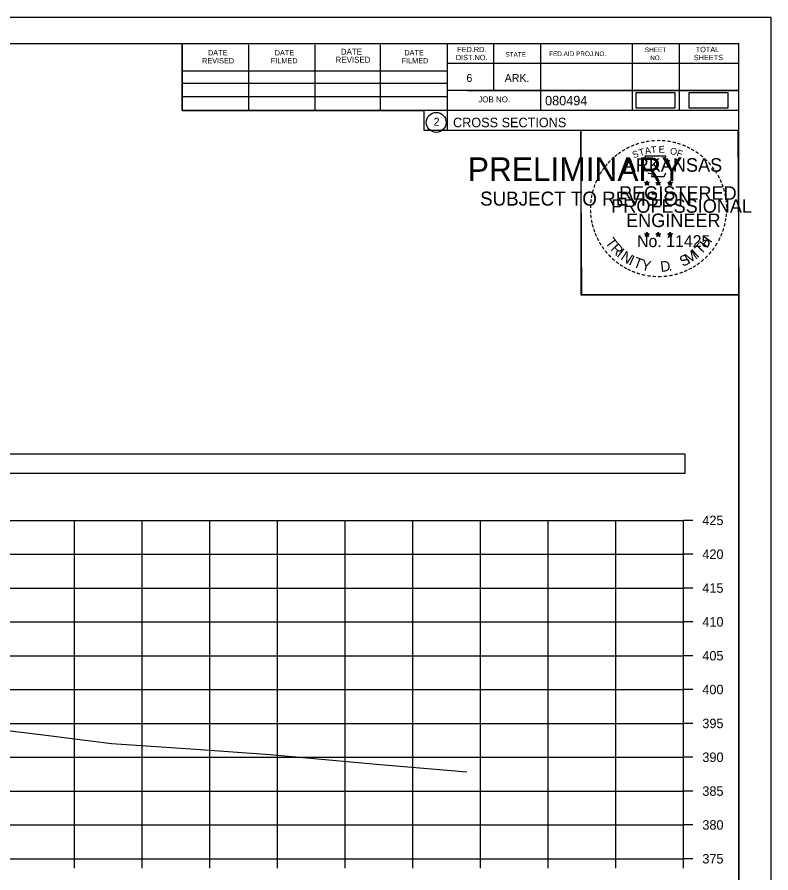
# Model space of a CAD drawing. Extents: x 1376273 to 1384221, y 378927 to 384592.
# Drawn here: x 1378276 to 1378387.4, y 380838.7 to 380965.2 of the extents above; entities that cross this region are included whole.
import ezdxf

# ---------------------------------------------------------------- set-up
doc = ezdxf.new("R2010")
doc.units = 0
for name, color, linetype in [('R_Axis', 7, 'Continuous'), ('R_Axis Annot', 7, 'Continuous'), ('R_Border', 7, 'Continuous'), ('R_Border PE', 7, 'Continuous'), ('R_Border Prem', 7, 'Continuous'), ('R_Drive', 7, 'Continuous'), ('R_Exist Surface', 7, 'Continuous'), ('R_Grid', 7, 'Continuous'), ('R_No Plot', 7, 'Continuous')]:
    doc.layers.add(name, color=color, linetype=linetype)

msp = doc.modelspace()

# ---------------------------------------------------------------- linework, layer by layer
at = {"layer": 'R_Axis'}
for p, q in [((1378374.46, 380840.83), (1378374.46, 380890.83)), ((1378375.86, 380890.83), (1378374.46, 380890.83)), ((1378375.86, 380885.83), (1378374.46, 380885.83)), ((1378375.86, 380880.83), (1378374.46, 380880.83)), ((1378375.86, 380875.83), (1378374.46, 380875.83)), ((1378375.86, 380870.83), (1378374.46, 380870.83)), ((1378375.86, 380865.83), (1378374.46, 380865.83)), ((1378375.86, 380860.83), (1378374.46, 380860.83)), ((1378375.86, 380855.83), (1378374.46, 380855.83)), ((1378375.86, 380850.83), (1378374.46, 380850.83)), ((1378375.86, 380845.83), (1378374.46, 380845.83)), ((1378074.46, 380840.83), (1378374.46, 380840.83)), ((1378284.46, 380839.43), (1378284.46, 380840.83)), ((1378294.46, 380839.43), (1378294.46, 380840.83)), ((1378304.46, 380839.43), (1378304.46, 380840.83)), ((1378314.46, 380839.43), (1378314.46, 380840.83)), ((1378324.46, 380839.43), (1378324.46, 380840.83)), ((1378334.46, 380839.43), (1378334.46, 380840.83)), ((1378344.46, 380839.43), (1378344.46, 380840.83)), ((1378354.46, 380839.43), (1378354.46, 380840.83)), ((1378364.46, 380839.43), (1378364.46, 380840.83)), ((1378374.46, 380839.43), (1378374.46, 380840.83)), ((1378375.86, 380840.83), (1378374.46, 380840.83))]:
    msp.add_line(p, q, dxfattribs=at)
at = {"layer": 'R_Axis Annot'}
msp.add_lwpolyline([(1378072.9, 380897.78), (1378374.7, 380897.78), (1378374.7, 380900.59), (1378072.9, 380900.59)], close=True, dxfattribs=at)
at = {"layer": 'R_Border'}
for p, q in [((1378066.46, 380961.29), (1378382.64, 380961.29)), ((1378300.38, 380951.41), (1378300.38, 380961.29)), ((1378339.54, 380961.29), (1378339.54, 380948.49)), ((1378346.38, 380961.29), (1378346.38, 380954.35)), ((1378353.32, 380961.29), (1378353.32, 380951.41)), ((1378366.9, 380961.29), (1378366.9, 380951.41)), ((1378373.84, 380961.29), (1378373.84, 380951.41)), ((1378382.64, 380755.83), (1378382.64, 380961.29)), ((1378310.24, 380951.41), (1378310.24, 380961.09)), ((1378320, 380951.41), (1378320, 380961.09)), ((1378329.68, 380951.41), (1378329.68, 380961.09)), ((1378382.64, 380958.35), (1378339.54, 380958.35)), ((1378382.64, 380958.37), (1378382.64, 380958.37)), ((1378300.38, 380957.27), (1378339.54, 380957.27)), ((1378300.38, 380955.41), (1378339.54, 380955.41)), ((1378382.64, 380954.35), (1378339.54, 380954.35)), ((1378342.5, 380954.35), (1378382.64, 380954.35)), ((1378300.38, 380951.41), (1378300.38, 380953.47)), ((1378300.38, 380953.47), (1378339.54, 380953.47)), ((1378382.64, 380951.41), (1378300.38, 380951.41)), ((1378339.54, 380948.49), (1378382.64, 380948.49))]:
    msp.add_line(p, q, dxfattribs=at)
msp.add_circle((1378337.92, 380949.63), 1.47, dxfattribs=at)
at = {"layer": 'R_Border PE'}
for p, q in [((1378368.72, 380940.75), (1378369.07, 380940.64)), ((1378368.72, 380940.75), (1378368.98, 380940.7)), ((1378368.72, 380940.75), (1378368.96, 380940.63)), ((1378368.86, 380940.34), (1378369.07, 380940.64)), ((1378368.86, 380940.34), (1378368.98, 380940.58)), ((1378368.86, 380940.34), (1378369.07, 380940.56)), ((1378369.07, 380941), (1378369.03, 380940.75)), ((1378369.07, 380940.64), (1378369.07, 380941)), ((1378369.07, 380941), (1378369.12, 380940.75)), ((1378369.42, 380940.75), (1378369.07, 380940.64)), ((1378369.28, 380940.34), (1378369.07, 380940.64)), ((1378369.28, 380940.34), (1378369.07, 380940.55)), ((1378369.42, 380940.75), (1378369.13, 380940.7)), ((1378369.28, 380940.34), (1378369.15, 380940.63)), ((1378369.42, 380940.75), (1378369.21, 380940.65)), ((1378370.39, 380940.75), (1378370.74, 380940.64)), ((1378370.39, 380940.75), (1378370.65, 380940.7)), ((1378370.39, 380940.75), (1378370.63, 380940.63)), ((1378370.53, 380940.34), (1378370.74, 380940.64)), ((1378370.53, 380940.34), (1378370.65, 380940.58)), ((1378370.53, 380940.34), (1378370.74, 380940.56)), ((1378370.74, 380941), (1378370.7, 380940.75)), ((1378370.74, 380940.64), (1378370.74, 380941)), ((1378370.74, 380941), (1378370.79, 380940.75)), ((1378371.09, 380940.75), (1378370.74, 380940.64)), ((1378370.95, 380940.34), (1378370.74, 380940.64)), ((1378370.95, 380940.34), (1378370.74, 380940.55)), ((1378371.09, 380940.75), (1378370.8, 380940.7)), ((1378370.95, 380940.34), (1378370.82, 380940.63)), ((1378371.09, 380940.75), (1378370.88, 380940.65)), ((1378372.16, 380940.74), (1378372.51, 380940.62)), ((1378372.16, 380940.74), (1378372.41, 380940.69)), ((1378372.16, 380940.74), (1378372.39, 380940.61)), ((1378372.29, 380940.33), (1378372.51, 380940.62)), ((1378372.29, 380940.33), (1378372.42, 380940.57)), ((1378372.29, 380940.33), (1378372.5, 380940.54)), ((1378372.51, 380940.99), (1378372.46, 380940.74)), ((1378372.72, 380940.33), (1378372.5, 380940.54)), ((1378372.51, 380940.62), (1378372.51, 380940.99)), ((1378372.51, 380940.99), (1378372.55, 380940.74)), ((1378372.85, 380940.74), (1378372.51, 380940.62)), ((1378372.72, 380940.33), (1378372.51, 380940.62)), ((1378372.85, 380940.74), (1378372.57, 380940.69)), ((1378372.72, 380940.33), (1378372.58, 380940.62)), ((1378372.85, 380940.74), (1378372.65, 380940.63)), ((1378368.72, 380933.17), (1378369.07, 380933.06)), ((1378368.72, 380933.17), (1378368.97, 380933.13)), ((1378368.72, 380933.17), (1378368.96, 380933.05)), ((1378368.85, 380932.77), (1378369.07, 380933.06)), ((1378368.85, 380932.77), (1378368.98, 380933.01)), ((1378368.85, 380932.77), (1378369.07, 380932.98)), ((1378369.07, 380933.43), (1378369.03, 380933.18)), ((1378369.07, 380933.06), (1378369.07, 380933.43)), ((1378369.07, 380933.43), (1378369.12, 380933.18)), ((1378369.41, 380933.17), (1378369.07, 380933.06)), ((1378369.28, 380932.77), (1378369.07, 380933.06)), ((1378369.28, 380932.77), (1378369.07, 380932.98)), ((1378369.41, 380933.17), (1378369.13, 380933.13)), ((1378369.28, 380932.77), (1378369.14, 380933.06)), ((1378369.41, 380933.17), (1378369.21, 380933.07)), ((1378370.39, 380933.17), (1378370.74, 380933.06)), ((1378370.39, 380933.17), (1378370.64, 380933.13)), ((1378370.39, 380933.17), (1378370.62, 380933.05)), ((1378370.52, 380932.77), (1378370.74, 380933.06)), ((1378370.52, 380932.77), (1378370.65, 380933.01)), ((1378370.52, 380932.77), (1378370.73, 380932.98)), ((1378370.74, 380933.43), (1378370.7, 380933.18)), ((1378370.95, 380932.77), (1378370.73, 380932.98)), ((1378370.74, 380933.06), (1378370.74, 380933.43)), ((1378370.74, 380933.43), (1378370.79, 380933.18)), ((1378371.08, 380933.17), (1378370.74, 380933.06)), ((1378370.95, 380932.77), (1378370.74, 380933.06)), ((1378371.08, 380933.17), (1378370.8, 380933.13)), ((1378370.95, 380932.77), (1378370.81, 380933.06)), ((1378371.08, 380933.17), (1378370.88, 380933.07)), ((1378372.15, 380933.16), (1378372.5, 380933.05)), ((1378372.15, 380933.16), (1378372.41, 380933.12)), ((1378372.15, 380933.16), (1378372.39, 380933.04)), ((1378372.29, 380932.76), (1378372.5, 380933.05)), ((1378372.29, 380932.76), (1378372.41, 380933)), ((1378372.29, 380932.76), (1378372.5, 380932.97)), ((1378372.5, 380933.42), (1378372.46, 380933.17)), ((1378372.5, 380933.05), (1378372.5, 380933.42)), ((1378372.5, 380933.42), (1378372.55, 380933.17)), ((1378372.85, 380933.16), (1378372.5, 380933.05)), ((1378372.72, 380932.76), (1378372.5, 380933.05)), ((1378372.72, 380932.76), (1378372.5, 380932.97)), ((1378372.85, 380933.16), (1378372.56, 380933.12)), ((1378372.72, 380932.76), (1378372.58, 380933.05)), ((1378372.85, 380933.16), (1378372.65, 380933.06))]:
    msp.add_line(p, q, dxfattribs=at)
for points in [[(1378368.76, 380944.63), (1378369.03, 380943.8)], [(1378372.27, 380943.7), (1378372.42, 380943.99), (1378371.73, 380943.96), (1378371.88, 380944.63), (1378368.76, 380944.63)], [(1378369.26, 380942.2), (1378369.26, 380942.12), (1378369.82, 380942.1), (1378369.76, 380941.62), (1378371.63, 380941.62), (1378371.84, 380942.16)], [(1378369.07, 380941), (1378369.28, 380940.34), (1378368.72, 380940.75), (1378369.42, 380940.75), (1378368.86, 380940.34), (1378369.07, 380941)], [(1378370.74, 380941), (1378370.95, 380940.34), (1378370.39, 380940.75), (1378371.09, 380940.75), (1378370.53, 380940.34), (1378370.74, 380941)], [(1378372.51, 380940.99), (1378372.72, 380940.33), (1378372.16, 380940.74), (1378372.85, 380940.74), (1378372.29, 380940.33), (1378372.51, 380940.99)], [(1378369.07, 380933.43), (1378369.28, 380932.77), (1378368.72, 380933.17), (1378369.41, 380933.17), (1378368.85, 380932.77), (1378369.07, 380933.43)], [(1378370.74, 380933.43), (1378370.95, 380932.77), (1378370.39, 380933.17), (1378371.08, 380933.17), (1378370.52, 380932.77), (1378370.74, 380933.43)], [(1378372.5, 380933.42), (1378372.72, 380932.76), (1378372.15, 380933.16), (1378372.85, 380933.16), (1378372.29, 380932.76), (1378372.5, 380933.42)]]:
    msp.add_lwpolyline(points, dxfattribs=at)
for centre, radius in [((1378369.07, 380940.64), 0.172), ((1378369.07, 380940.64), 0.145), ((1378369.07, 380940.64), 0.116), ((1378369.07, 380940.64), 0.0991), ((1378369.07, 380940.64), 0.0747), ((1378369.07, 380940.64), 0.0495), ((1378369.07, 380940.64), 0.0296), ((1378370.74, 380940.64), 0.172), ((1378370.74, 380940.64), 0.145), ((1378370.74, 380940.64), 0.116), ((1378370.74, 380940.64), 0.0991), ((1378370.74, 380940.64), 0.0747), ((1378370.74, 380940.64), 0.0495), ((1378370.74, 380940.64), 0.0296), ((1378372.5, 380940.62), 0.172), ((1378372.5, 380940.62), 0.145), ((1378372.5, 380940.62), 0.116), ((1378372.5, 380940.62), 0.0991), ((1378372.5, 380940.62), 0.0747), ((1378372.5, 380940.62), 0.0495), ((1378372.5, 380940.62), 0.0296), ((1378369.07, 380933.06), 0.172), ((1378369.07, 380933.06), 0.145), ((1378369.07, 380933.06), 0.116), ((1378369.07, 380933.06), 0.0991), ((1378369.07, 380933.06), 0.0747), ((1378369.07, 380933.06), 0.0495), ((1378369.07, 380933.06), 0.0296), ((1378370.74, 380933.06), 0.172), ((1378370.74, 380933.06), 0.145), ((1378370.74, 380933.06), 0.116), ((1378370.74, 380933.06), 0.0991), ((1378370.74, 380933.06), 0.0747), ((1378370.74, 380933.06), 0.0495), ((1378370.74, 380933.06), 0.0296), ((1378372.5, 380933.05), 0.172), ((1378372.5, 380933.05), 0.145), ((1378372.5, 380933.05), 0.116), ((1378372.5, 380933.05), 0.0991), ((1378372.5, 380933.05), 0.0747), ((1378372.5, 380933.05), 0.0495), ((1378372.5, 380933.05), 0.0296)]:
    msp.add_circle(centre, radius, dxfattribs=at)
at = {"layer": 'R_Drive'}
for points in [[(1378367.43, 380951.8), (1378373.26, 380951.8), (1378373.26, 380953.99), (1378367.43, 380953.99)], [(1378375.24, 380951.79), (1378381.08, 380951.79), (1378381.08, 380953.98), (1378375.24, 380953.98)]]:
    msp.add_lwpolyline(points, close=True, dxfattribs=at)
at = {"layer": 'R_Exist Surface'}
msp.add_lwpolyline([(1378270.5, 380860.27), (1378280.62, 380859.02), (1378289.91, 380857.87), (1378302.37, 380857), (1378313.37, 380856.25), (1378329.1, 380854.81), (1378342.46, 380853.66)], dxfattribs=at)
at = {"layer": 'R_Grid'}
for p, q in [((1378074.46, 380890.83), (1378374.46, 380890.83)), ((1378284.46, 380840.83), (1378284.46, 380890.83)), ((1378294.46, 380840.83), (1378294.46, 380890.83)), ((1378304.46, 380840.83), (1378304.46, 380890.83)), ((1378314.46, 380840.83), (1378314.46, 380890.83)), ((1378324.46, 380840.83), (1378324.46, 380890.83)), ((1378334.46, 380840.83), (1378334.46, 380890.83)), ((1378344.46, 380840.83), (1378344.46, 380890.83)), ((1378354.46, 380840.83), (1378354.46, 380890.83)), ((1378364.46, 380840.83), (1378364.46, 380890.83)), ((1378374.46, 380840.83), (1378374.46, 380890.83)), ((1378074.46, 380885.83), (1378374.46, 380885.83)), ((1378074.46, 380880.83), (1378374.46, 380880.83)), ((1378074.46, 380875.83), (1378374.46, 380875.83)), ((1378074.46, 380870.83), (1378374.46, 380870.83)), ((1378074.46, 380865.83), (1378374.46, 380865.83)), ((1378074.46, 380860.83), (1378374.46, 380860.83)), ((1378074.46, 380855.83), (1378374.46, 380855.83)), ((1378074.46, 380850.83), (1378374.46, 380850.83)), ((1378074.46, 380845.83), (1378374.46, 380845.83)), ((1378074.46, 380840.83), (1378374.46, 380840.83))]:
    msp.add_line(p, q, dxfattribs=at)
at = {"layer": 'R_No Plot'}
for p, q in [((1378054.06, 380965.19), (1378387.39, 380965.19)), ((1378358.67, 380926.04), (1378358.67, 380926.04))]:
    msp.add_line(p, q, dxfattribs=at)
for points in [[(1378054.05, 380965.19), (1378387.39, 380965.19), (1378387.39, 380751.85), (1378054.05, 380751.85)], [(1378300.38, 380961.29), (1378300.38, 380951.41), (1378336.11, 380951.41), (1378336.11, 380948.49), (1378359.31, 380948.49), (1378359.31, 380924.16), (1378382.64, 380924.16), (1378382.64, 380755.83), (1378066.46, 380755.83), (1378066.46, 380961.29)], [(1378359.31, 380948.49), (1378382.52, 380948.49), (1378382.64, 380924.16), (1378359.43, 380924.16)]]:
    msp.add_lwpolyline(points, close=True, dxfattribs=at)

# ---------------------------------------------------------------- texts
at = {"layer": 'R_Axis Annot'}
for s, p in [('425', (1378377.26, 380890.13)), ('420', (1378377.26, 380885.13)), ('415', (1378377.26, 380880.13)), ('410', (1378377.26, 380875.13)), ('405', (1378377.26, 380870.13)), ('400', (1378377.26, 380865.13)), ('395', (1378377.26, 380860.13)), ('390', (1378377.26, 380855.13)), ('385', (1378377.26, 380850.13)), ('380', (1378377.26, 380845.13)), ('375', (1378377.26, 380840.13))]:
    msp.add_text(s, height=1.4, dxfattribs=at).set_placement(p)
at = {"layer": 'R_Border'}
for s, height, p in [('DATE', 0.782, (1378304.18, 380959.53)), ('DATE', 0.782, (1378314.04, 380959.53)), ('DATE', 0.879, (1378323.82, 380959.63)), ('DATE', 0.782, (1378333.2, 380959.53)), ('FED.RD.', 0.782, (1378341.02, 380960.01)), ('STATE', 0.684, (1378348.14, 380959.33)), ('FED.AID PROJ.NO.', 0.684, (1378354.6, 380959.43)), ('SHEET', 0.684, (1378368.76, 380960.01)), ('TOTAL', 0.782, (1378376.28, 380960.01)), ('REVISED', 0.782, (1378303.3, 380958.35)), ('FILMED', 0.782, (1378313.46, 380958.35)), ('REVISED', 0.879, (1378323.04, 380958.45)), ('FILMED', 0.782, (1378332.8, 380958.35)), ('DIST.NO.', 0.782, (1378340.82, 380958.83)), ('NO.', 0.684, (1378369.54, 380958.83)), ('SHEETS', 0.782, (1378376, 380958.83)), ('6', 1.17, (1378342.38, 380955.61)), ('ARK.', 1.172, (1378348.04, 380955.61)), ('JOB NO.', 0.879, (1378344.14, 380952.59)), ('080494', 1.4, (1378354.01, 380952.15)), ('2', 1.17, (1378337.54, 380949.14)), ('CROSS SECTIONS', 1.4, (1378340.4, 380948.92))]:
    msp.add_text(s, height=height, rotation=360, dxfattribs=at).set_placement(p)
at = {"layer": 'R_Border PE'}
for s, height, rotation, p in [('-', 1.6, 24.3072, (1378366.88, 380945.48)), ('-', 1.6, 19.1761, (1378367.51, 380945.75)), ('-', 1.6, 13.6301, (1378368.26, 380945.99)), ('-', 1.6, 10.2193, (1378368.94, 380946.16)), ('T', 1, 6.0228, (1378369.71, 380945.05)), ('-', 1.6, 5.8968, (1378369.67, 380946.27)), ('-', 1.6, 0.1862, (1378370.44, 380946.34)), ('E', 1, 0.8323, (1378370.81, 380945.16)), ('-', 1.6, 357.743, (1378371.16, 380946.32)), ('-', 1.6, 352.1617, (1378371.91, 380946.27)), ('-', 1.6, 347.2049, (1378372.63, 380946.15)), ('-', 1.6, 342.3362, (1378373.26, 380946)), ('-', 1.6, 337.8551, (1378374, 380945.78)), ('-', 1.6, 38.9507, (1378364.59, 380944.02)), ('-', 1.6, 36.2317, (1378365.07, 380944.4)), ('-', 1.6, 34.0636, (1378365.65, 380944.8)), ('-', 1.6, 28.7918, (1378366.24, 380945.17)), ('S', 1, 21.594, (1378367.12, 380944.3)), ('T', 1, 16.4036, (1378368.03, 380944.63)), ('A', 1, 11.2132, (1378368.86, 380944.89)), ('O', 1, 350.4515, (1378372.42, 380944.95)), ('F', 1, 340.0707, (1378373.37, 380944.72)), ('-', 1.6, 334.1211, (1378374.63, 380945.51)), ('-', 1.6, 329.6409, (1378375.21, 380945.22)), ('-', 1.6, 325.8627, (1378375.85, 380944.86)), ('-', 1.6, 320.5297, (1378376.46, 380944.44)), ('-', 1.6, 48.423, (1378363.71, 380943.13)), ('-', 1.6, 42.9622, (1378364.16, 380943.61)), ('ARKANSAS', 2, 360, (1378365.62, 380942.34)), ('-', 1.6, 315.5786, (1378377.06, 380943.95)), ('-', 1.6, 309.8797, (1378377.63, 380943.4)), ('-', 1.6, 58.0706, (1378362.57, 380941.55)), ('-', 1.6, 54.2325, (1378362.9, 380942.08)), ('-', 1.6, 50.6142, (1378363.31, 380942.64)), ('-', 1.6, 306.6522, (1378378.15, 380942.8)), ('-', 1.4, 303.6753, (1378378.64, 380942.23)), ('-', 1.6, 67.7743, (1378362, 380940.32)), ('-', 1.6, 62.8713, (1378362.26, 380940.93)), ('-', 1.6, 299.6684, (1378378.96, 380941.62)), ('-', 1.6, 294.6628, (1378379.28, 380941.01)), ('-', 1.6, 72.3945, (1378361.78, 380939.69)), ('REGISTERED', 2, 360, (1378364.94, 380938.19)), ('DWB', 0.01, 360, (1378369.06, 380940.63)), ('DWB', 0.01, 360, (1378370.73, 380940.63)), ('DWB', 0.01, 360, (1378372.49, 380940.62)), ('-', 1.6, 290.5728, (1378379.54, 380940.43)), ('-', 1.6, 285.1233, (1378379.77, 380939.85)), ('-', 1.6, 81.2013, (1378361.45, 380938.27)), ('-', 1.6, 75.461, (1378361.58, 380938.98)), ('-', 1.6, 280.5493, (1378379.97, 380939.11)), ('-', 1.6, 89.0622, (1378361.35, 380936.87)), ('-', 1.6, 85.1863, (1378361.37, 380937.58)), ('PROFESSIONAL', 2, 360, (1378363.79, 380936.28)), ('-', 1.6, 276.5962, (1378380.13, 380938.34)), ('-', 1.6, 274.3301, (1378380.19, 380937.62)), ('-', 1.6, 94.1959, (1378361.38, 380936.15)), ('-', 1.6, 98.9479, (1378361.46, 380935.48)), ('ENGINEER', 2, 360, (1378365.98, 380934.16)), ('-', 1.6, 263.5172, (1378380.21, 380936.32)), ('-', 1.6, 269.9407, (1378380.23, 380936.99)), ('-', 1.6, 101.7149, (1378361.59, 380934.75)), ('-', 1.6, 255.7626, (1378380.03, 380934.99)), ('-', 1.6, 260.9953, (1378380.14, 380935.67)), ('-', 1.6, 105.4578, (1378361.75, 380934.15)), ('-', 1.6, 109.0874, (1378361.97, 380933.52)), ('-', 1.6, 252.8681, (1378379.85, 380934.27)), ('-', 1.6, 114.0643, (1378362.22, 380932.93)), ('-', 1.6, 115.7289, (1378362.53, 380932.31)), ('T', 1.54, 306.0406, (1378362.83, 380931.9)), ('No. 11425', 1.757, 360, (1378367.6, 380931.21)), ('DWB', 0.01, 360, (1378369.05, 380933.06)), ('DWB', 0.01, 360, (1378370.72, 380933.06)), ('DWB', 0.01, 360, (1378372.49, 380933.05)), ('H', 1.54, 54.6088, (1378377.95, 380930.94)), ('-', 1.6, 244.6197, (1378379.36, 380932.97)), ('-', 1.6, 247.8887, (1378379.62, 380933.6)), ('-', 1.6, 120.4471, (1378362.88, 380931.72)), ('-', 1.6, 125.8934, (1378363.29, 380931.16)), ('R', 1.54, 314.005, (1378363.59, 380930.85)), ('I', 1.54, 321.9694, (1378364.49, 380929.92)), ('T', 1.54, 46.6444, (1378377.06, 380929.99)), ('-', 1.6, 233.8452, (1378378.57, 380931.56)), ('-', 1.6, 239.0712, (1378378.97, 380932.22)), ('-', 1.6, 130.7181, (1378363.75, 380930.61)), ('-', 1.6, 134.2238, (1378364.27, 380930.07)), ('N', 1.54, 326.5002, (1378365.06, 380929.45)), ('I', 1.54, 335.3603, (1378366.26, 380928.66)), ('T', 1.54, 339.8912, (1378366.93, 380928.34)), ('S', 1.54, 26.9312, (1378374.37, 380928.26)), ('M', 1.54, 32.6563, (1378375.21, 380928.67)), ('I', 1.54, 42.1136, (1378376.5, 380929.52)), ('-', 1.6, 225.7653, (1378377.66, 380930.43)), ('-', 1.6, 231.2538, (1378378.14, 380931)), ('-', 1.6, 138.9338, (1378364.79, 380929.6)), ('-', 1.6, 144.6463, (1378365.35, 380929.2)), ('-', 1.6, 148.0898, (1378365.91, 380928.82)), ('Y', 1.54, 347.8556, (1378368.14, 380927.89)), ('D', 1.54, 6.3969, (1378371.13, 380927.53)), ('-', 1.6, 212.2491, (1378376.05, 380929.06)), ('-', 1.6, 215.7363, (1378376.59, 380929.45)), ('-', 1.6, 221.0851, (1378377.13, 380929.92)), ('-', 1.6, 151.5704, (1378366.49, 380928.5)), ('-', 1.6, 154.6002, (1378367.01, 380928.25)), ('-', 1.6, 158.5612, (1378367.63, 380928)), ('-', 1.6, 162.7983, (1378368.32, 380927.79)), ('-', 1.6, 167.5555, (1378369.04, 380927.62)), ('-', 1.6, 191.2858, (1378372.84, 380927.69)), ('.', 1.54, 13.7642, (1378372.32, 380927.66)), ('-', 1.6, 195.4743, (1378373.57, 380927.88)), ('-', 1.6, 200.7184, (1378374.25, 380928.13)), ('-', 1.6, 204.2516, (1378374.87, 380928.4)), ('-', 1.6, 207.3568, (1378375.49, 380928.72)), ('-', 1.6, 173.1155, (1378369.81, 380927.51)), ('-', 1.6, 176.5183, (1378370.56, 380927.46)), ('-', 1.6, 181.5918, (1378371.3, 380927.48)), ('-', 1.6, 185.8167, (1378372.11, 380927.55))]:
    msp.add_text(s, height=height, rotation=rotation, dxfattribs=at).set_placement(p)
at = {"layer": 'R_Border Prem'}
for s, height, p in [('PRELIMINARY', 3.5, (1378342.59, 380940.96)), ('DWB', 0.01, (1378343.33, 380942.8)), ('SUBJECT TO REVISION', 2.0751, (1378344.4, 380937.33))]:
    msp.add_text(s, height=height, rotation=360, dxfattribs=at).set_placement(p)

doc.saveas('drawing.dxf')
